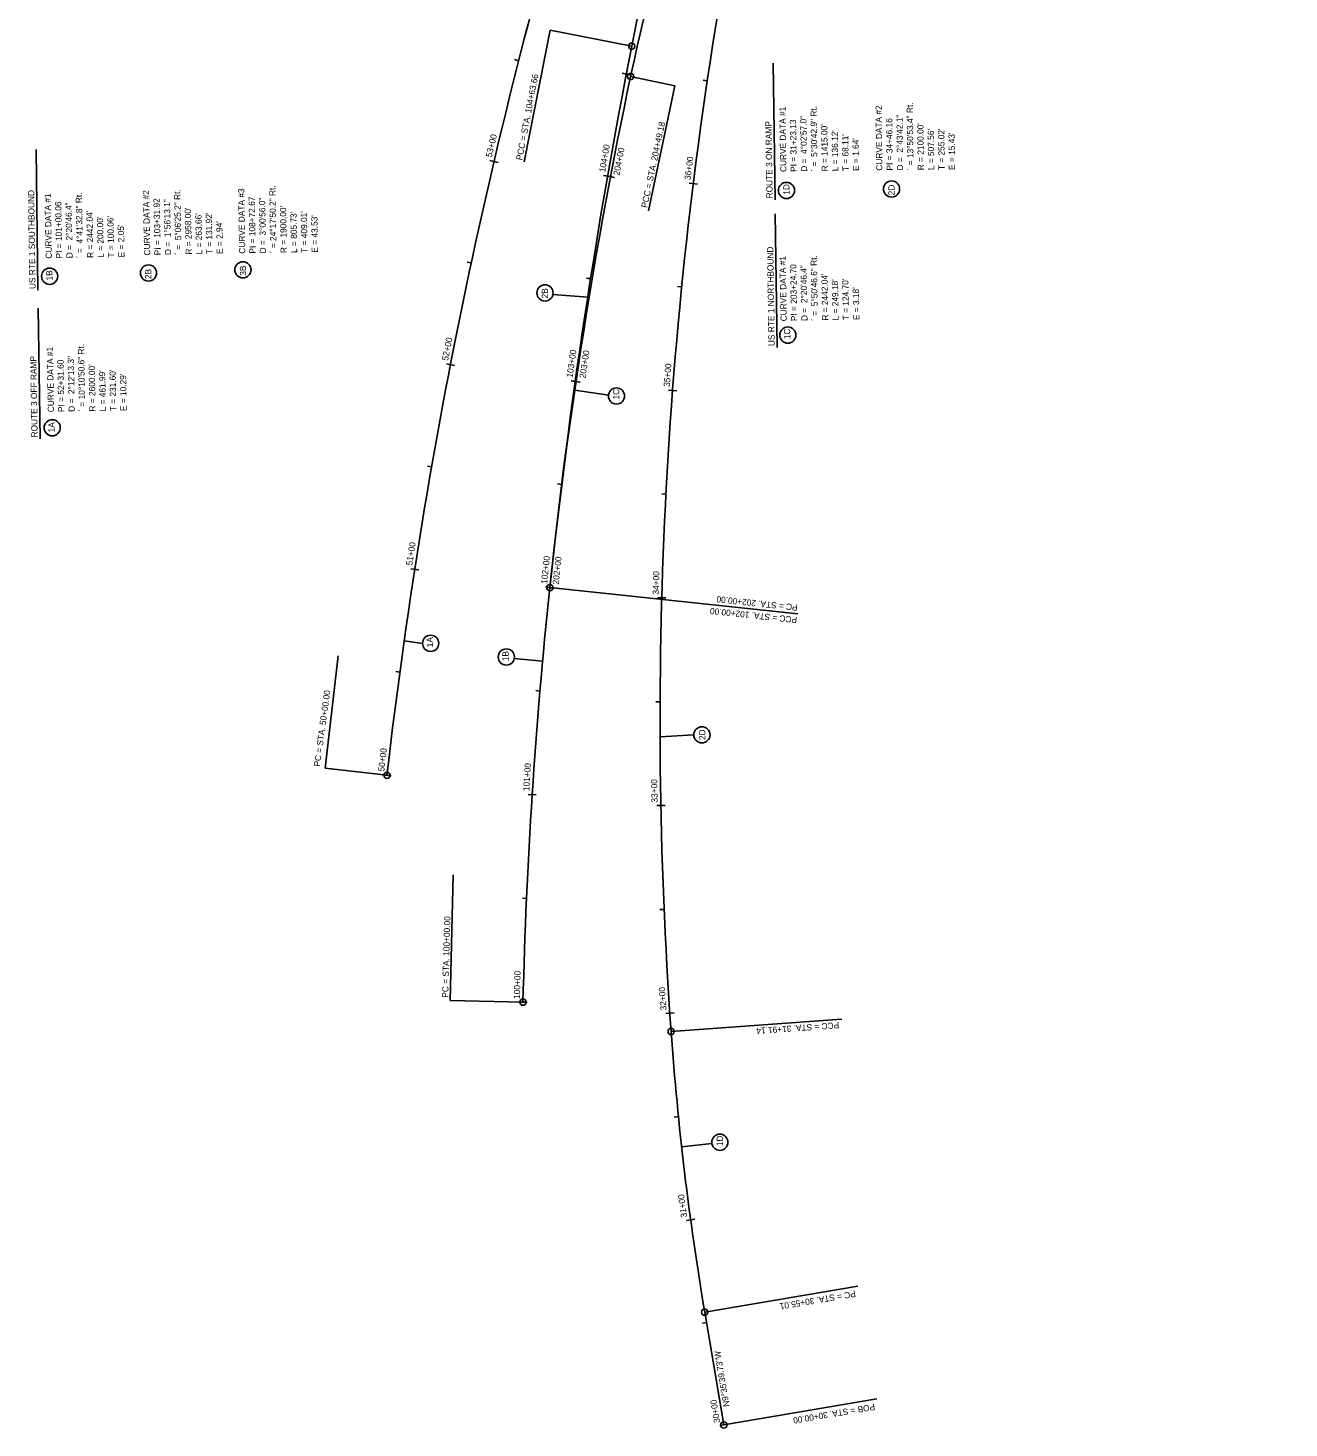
# Model space of a CAD drawing. Extents: x 1667099 to 1669772, y 337408 to 340124.
# Drawn here: x 1667099 to 1667706, y 337408 to 338082 of the extents above; entities that cross this region are included whole.
import ezdxf

# ---------------------------------------------------------------- set-up
doc = ezdxf.new("R2010")
doc.units = 0
for name, color, linetype in [('Alignment', 7, 'Continuous'), ('ANNOTATION', 7, 'Continuous'), ('D_Roadway_Centerline', 7, 'Continuous'), ('D_Roadway_Centerline_Bearings', 7, 'Continuous'), ('D_Roadway_Centerline_CurveData', 7, 'Continuous'), ('D_Roadway_Centerline_Flags', 7, 'Continuous'), ('D_Roadway_Centerline_Text', 7, 'Continuous'), ('S_Roadway_Edge_Pavement', 7, 'Continuous')]:
    doc.layers.add(name, color=color, linetype=linetype)

msp = doc.modelspace()

# ---------------------------------------------------------------- linework, layer by layer
at = {"layer": 'Alignment'}
msp.add_line((1667434.31, 337409.38), (1667425.14, 337463.63), dxfattribs=at)
for centre, radius, start, end in [((1668999.64, 337703.58), 1648.86, 162.88335, 167.57328), ((1669854.92, 337423.57), 2600, 163.22657, 173.40729), ((1669503.61, 337748.23), 2100, 170.2343, 184.08246), ((1669778.96, 337554.79), 2442.04, 168.09878, 173.94506), ((1668820.35, 337699.47), 1415, 184.08246, 189.59437)]:
    msp.add_arc(centre, radius, start, end, dxfattribs=at)
at = {"layer": 'ANNOTATION'}
for p, q in [((1667458.98, 337999.1), (1667458.07, 338064.76)), ((1667104.07, 337955.48), (1667103.13, 338023.31)), ((1667459.96, 337928.02), (1667459.07, 337992.36)), ((1667352.05, 337953.49), (1667368.76, 337952.25)), ((1667105.06, 337884.03), (1667104.19, 337946.87)), ((1667378.75, 337905.02), (1667362.51, 337907.39)), ((1667289.28, 337785.5), (1667280.41, 337786.75)), ((1667333.44, 337778.22), (1667347.05, 337776.98)), ((1667419.86, 337741.46), (1667403.63, 337740.54)), ((1667428.55, 337544.75), (1667413.87, 337543.27))]:
    msp.add_line(p, q, dxfattribs=at)
for centre in [(1667464.47, 338003.55), (1667515.07, 338004.24), (1667109.68, 337962.24), (1667157.3, 337963.83), (1667202.76, 337965.33), (1667348.22, 337954.22), (1667465.14, 337933.93), (1667382.63, 337904.6), (1667110.94, 337889.31), (1667293.18, 337785.55), (1667329.61, 337778.96), (1667423.76, 337741.51), (1667432.4, 337545.42)]:
    msp.add_circle(centre, 3.9, dxfattribs=at)
at = {"layer": 'D_Roadway_Centerline'}
msp.add_line((1667434.31, 337409.38), (1667425.14, 337463.63), dxfattribs=at)
for centre, radius, start, end in [((1669254.06, 337705.17), 1900, 144.54079, 168.83807), ((1668999.64, 337703.58), 1648.86, 162.88335, 167.57328), ((1669854.92, 337423.57), 2600, 163.22657, 173.40729), ((1669503.61, 337748.23), 2100, 170.2343, 184.08246), ((1670292.04, 337500.36), 2958, 168.83807, 173.94506), ((1669778.96, 337554.79), 2442.04, 168.09878, 173.94506), ((1669778.96, 337554.79), 2442.04, 173.94506, 178.63751), ((1668820.35, 337699.47), 1415, 184.08246, 189.59437)]:
    msp.add_arc(centre, radius, start, end, dxfattribs=at)
at = {"layer": 'D_Roadway_Centerline_Flags'}
for p, q in [((1667350.75, 338080.72), (1667338.23, 338017.24)), ((1667410.7, 338053.91), (1667398.02, 337993.75)), ((1667248.56, 337779.58), (1667242.31, 337725.52)), ((1667302.62, 337613.68), (1667304.06, 337674.09))]:
    msp.add_line(p, q, dxfattribs=at)
for points in [[(1667350.75, 338080.72), (1667390, 338072.98)], [(1667389.41, 338058.4), (1667410.7, 338053.91)], [(1667350.54, 337812.38), (1667469.88, 337799.72)], [(1667350.54, 337812.38), (1667469.88, 337799.72)], [(1667242.31, 337725.52), (1667272.11, 337722.07)], [(1667302.62, 337613.68), (1667337.61, 337612.85)], [(1667408.94, 337598.73), (1667491.21, 337604.6)], [(1667425.14, 337463.63), (1667498.87, 337476.09)], [(1667508.04, 337421.85), (1667434.31, 337409.38)]]:
    msp.add_lwpolyline(points, dxfattribs=at)
for centre in [(1667390, 338072.98), (1667389.41, 338058.4), (1667350.54, 337812.38), (1667350.54, 337812.38), (1667272.11, 337722.07), (1667337.61, 337612.85), (1667408.94, 337598.73), (1667425.14, 337463.63), (1667434.31, 337409.38)]:
    msp.add_circle(centre, 1.5, dxfattribs=at)
at = {"layer": 'D_Roadway_Centerline_Text'}
for points in [[(1667333.6, 338066.5), (1667335.54, 338066.01)], [(1667385.42, 338059.95), (1667387.38, 338059.57)], [(1667387.64, 338059.63), (1667389.59, 338059.2)], [(1667424.36, 338056.64), (1667426.34, 338056.35)], [(1667321.71, 338017.9), (1667325.6, 338016.99)], [(1667376.38, 338010.74), (1667380.32, 338010.05)], [(1667377.79, 338010.55), (1667381.72, 338009.8)], [(1667417.61, 338007.06), (1667421.58, 338006.56)], [(1667310.75, 337969.08), (1667312.7, 337968.66)], [(1667368.17, 337961.39), (1667370.14, 337961.08)], [(1667368.96, 337961.29), (1667370.94, 337960.96)], [(1667412.04, 337957.32), (1667414.03, 337957.12)], [(1667300.73, 337920.05), (1667304.65, 337919.29)], [(1667360.79, 337911.9), (1667364.75, 337911.34)], [(1667361.15, 337911.87), (1667365.1, 337911.28)], [(1667407.65, 337907.47), (1667411.64, 337907.16)], [(1667291.65, 337870.85), (1667293.62, 337870.5)], [(1667354.25, 337862.3), (1667356.24, 337862.05)], [(1667354.34, 337862.29), (1667356.33, 337862.04)], [(1667404.46, 337857.52), (1667406.45, 337857.42)], [(1667283.53, 337821.47), (1667287.48, 337820.86)], [(1667348.56, 337812.59), (1667352.53, 337812.17)], [(1667348.56, 337812.59), (1667352.53, 337812.17)], [(1667402.45, 337807.52), (1667406.45, 337807.4)], [(1667276.35, 337771.95), (1667278.33, 337771.68)], [(1667343.79, 337762.78), (1667345.78, 337762.61)], [(1667401.63, 337757.48), (1667403.63, 337757.47)], [(1667270.13, 337722.3), (1667274.1, 337721.84)], [(1667340.04, 337712.88), (1667344.03, 337712.62)], [(1667402.01, 337707.43), (1667406.01, 337707.51)], [(1667337.31, 337662.91), (1667339.31, 337662.82)], [(1667403.58, 337657.41), (1667405.57, 337657.5)], [(1667335.61, 337612.9), (1667339.61, 337612.8)], [(1667406.33, 337607.44), (1667410.33, 337607.71)], [(1667410.48, 337557.55), (1667412.47, 337557.75)], [(1667416.37, 337507.83), (1667420.33, 337508.37)], [(1667424.01, 337458.35), (1667425.98, 337458.69)], [(1667432.34, 337409.05), (1667436.29, 337409.72)]]:
    msp.add_lwpolyline(points, dxfattribs=at)
at = {"layer": 'S_Roadway_Edge_Pavement'}
for centre, radius, start, end in [((1669254.06, 337705.17), 1900, 144.54079, 168.83807), ((1670292.04, 337500.36), 2958, 168.83807, 173.94506), ((1669778.96, 337554.79), 2442.04, 173.94506, 178.63751)]:
    msp.add_arc(centre, radius, start, end, dxfattribs=at)

# ---------------------------------------------------------------- texts
at = {"layer": 'ANNOTATION'}
for s, rotation, p in [('ROUTE 3 ON RAMP', 90.79092, (1667457.82, 337999.72)), ('US RTE 1 SOUTHBOUND', 90.79092, (1667102.91, 337956.1)), ('1D', 90.79092, (1667465.98, 338001.48)), ('2D', 90.79092, (1667516.58, 338001.22)), ('US RTE 1 NORTHBOUND', 90.79092, (1667458.8, 337928.64)), ('1B', 90.79092, (1667111.09, 337960.22)), ('2B', 90.79092, (1667158.68, 337960.88)), ('3B', 91.23053, (1667204.34, 337962.52)), ('2B', 90.79092, (1667349.65, 337951.57)), ('1C', 90.79092, (1667466.3, 337931.96)), ('ROUTE 3 OFF RAMP', 90.79092, (1667103.9, 337884.66)), ('1C', 90.79092, (1667383.99, 337902.91)), ('1A', 90.79092, (1667112.1, 337887.08)), ('1A', 90.79092, (1667294.3, 337783.67)), ('1B', 90.79092, (1667330.72, 337776.99)), ('2D', 90.79092, (1667425.47, 337739.02)), ('1D', 90.79092, (1667433.88, 337543.56))]:
    msp.add_text(s, height=3, rotation=rotation, dxfattribs=at).set_placement(p)
at = {"layer": 'D_Roadway_Centerline_Bearings'}
msp.add_text('N9%%d35\'39.73"W', height=3, rotation=99.59437, dxfattribs=at).set_placement((1667437.12, 337418.38))
at = {"layer": 'D_Roadway_Centerline_CurveData'}
for s, rotation, p in [('CURVE DATA #1', 90.81635, (1667464.46, 338012.44)), ('´ =  5%%d30\'42.9" Rt.', 90.81635, (1667479.46, 338012.65)), ('CURVE DATA #2', 90.54783, (1667510.66, 338013.08)), ('´ = 13%%d50\'53.4" Rt.', 90.54783, (1667525.66, 338013.22)), ('PI = 31+23.13', 90.81635, (1667469.46, 338012.51)), ('D =  4%%d02\'57.0"', 90.81635, (1667474.46, 338012.58)), ('PI = 34+46.16', 90.54783, (1667515.66, 338013.13)), ('D =  2%%d43\'42.1"', 90.54783, (1667520.66, 338013.17)), ("R = 1415.00'", 90.81635, (1667484.46, 338012.73)), ("L = 136.12'", 90.81635, (1667489.46, 338012.8)), ("T = 68.11'", 90.81635, (1667494.46, 338012.87)), ("R = 2100.00'", 90.54783, (1667530.66, 338013.27)), ("L = 507.56'", 90.54783, (1667535.66, 338013.32)), ("T = 255.02'", 90.54783, (1667540.66, 338013.37)), ("E = 15.43'", 90.54783, (1667545.66, 338013.41)), ("E = 1.64'", 90.81635, (1667499.46, 338012.94)), ('CURVE DATA #2', 91.13691, (1667158.19, 337972.28)), ('´ =  5%%d06\'25.2" Rt.', 91.13691, (1667173.19, 337972.58)), ('CURVE DATA #3', 90.84556, (1667203.9, 337973.11)), ('´ = 24%%d17\'50.2" Rt.', 90.84556, (1667218.9, 337973.33)), ('CURVE DATA #1', 91.03265, (1667110.77, 337970.74)), ('PI = 101+00.06', 91.03265, (1667115.77, 337970.83)), ('D =  2%%d20\'46.4"', 91.03265, (1667120.77, 337970.92)), ('´ =  4%%d41\'32.8" Rt.', 91.03265, (1667125.77, 337971.01)), ('PI = 103+31.92', 91.13691, (1667163.19, 337972.38)), ('D =  1%%d56\'13.1"', 91.13691, (1667168.19, 337972.48)), ('PI = 108+72.67', 90.84556, (1667208.9, 337973.18)), ('D =  3%%d00\'56.0"', 90.84556, (1667213.9, 337973.26)), ("R = 2442.04'", 91.03265, (1667130.77, 337971.1)), ("L = 200.00'", 91.03265, (1667135.77, 337971.19)), ("T = 100.06'", 91.03265, (1667140.77, 337971.28)), ("R = 2958.00'", 91.13691, (1667178.19, 337972.68)), ("L = 263.66'", 91.13691, (1667183.18, 337972.78)), ("T = 131.92'", 91.13691, (1667188.18, 337972.88)), ("R = 1900.00'", 90.84556, (1667223.9, 337973.41)), ("L = 805.73'", 90.84556, (1667228.9, 337973.48)), ("T = 409.01'", 90.84556, (1667233.9, 337973.55)), ("E = 43.53'", 90.84556, (1667238.9, 337973.63)), ("E = 2.05'", 91.03265, (1667145.76, 337971.37)), ("E = 2.94'", 91.13691, (1667193.18, 337972.98)), ('CURVE DATA #1', 90.96311, (1667464.63, 337940.57)), ('´ =  5%%d50\'46.6" Rt.', 90.96311, (1667479.63, 337940.83)), ('PI = 203+24.70', 90.96311, (1667469.63, 337940.66)), ('D =  2%%d20\'46.4"', 90.96311, (1667474.63, 337940.74)), ("R = 2442.04'", 90.96311, (1667484.63, 337940.91)), ("L = 249.18'", 90.96311, (1667489.63, 337941)), ("T = 124.70'", 90.96311, (1667494.63, 337941.08)), ("E = 3.18'", 90.96311, (1667499.63, 337941.16)), ('´ = 10%%d10\'50.6" Rt.', 90.91268, (1667126.79, 337897.07)), ('CURVE DATA #1', 90.91268, (1667111.79, 337896.83)), ('D =  2%%d12\'13.3"', 90.91268, (1667121.79, 337896.99)), ('PI = 52+31.60', 90.91268, (1667116.79, 337896.91)), ("R = 2600.00'", 90.91268, (1667131.79, 337897.15)), ("L = 461.99'", 90.91268, (1667136.79, 337897.23)), ("T = 231.60'", 90.91268, (1667141.79, 337897.31)), ("E = 10.29'", 90.91268, (1667146.79, 337897.39))]:
    msp.add_text(s, height=3, rotation=rotation, dxfattribs=at).set_placement(p)
at = {"layer": 'D_Roadway_Centerline_Flags'}
for s, rotation, p in [('PCC = STA. 104+63.66', 79.20181, (1667337.19, 338017.9)), ('PCC = STA. 204+49.18', 78.09878, (1667397.42, 337994.99)), ('PC = STA. 202+00.00', 173.94506, (1667470, 337804.19)), ('PCC = STA. 102+00.00', 173.94506, (1667469.72, 337798.23)), ('PC = STA. 50+00.00', 82.15547, (1667239.83, 337726.08)), ('PC = STA. 100+00.00', 88.46468, (1667301.61, 337614.95)), ('PCC = STA. 31+91.14', 184.08246, (1667489.73, 337603.29)), ('PC = STA. 30+55.01', 189.59437, (1667497.51, 337474.02)), ('POB = STA. 30+00.00', 189.59437, (1667506.84, 337419.58))]:
    msp.add_text(s, height=3, rotation=rotation, dxfattribs=at).set_placement(p)
at = {"layer": 'D_Roadway_Centerline_Text'}
for s, rotation, p in [('53+00', 76.79624, (1667322.54, 338019.25)), ('104+00', 80.07111, (1667377.13, 338012.13)), ('204+00', 79.25261, (1667384.01, 338010.61)), ('36+00', 82.92713, (1667418.29, 338008.48)), ('52+00', 78.99992, (1667301.5, 337921.43)), ('103+00', 82.00808, (1667361.49, 337913.32)), ('203+00', 81.59884, (1667367.67, 337912.99)), ('35+00', 85.65551, (1667408.27, 337908.92)), ('51+00', 81.20361, (1667284.25, 337822.88)), ('102+00', 83.94506, (1667349.21, 337814.03)), ('202+00', 83.94506, (1667354.82, 337813.77)), ('34+00', 88.38388, (1667402.99, 337809)), ('50+00', 83.40729, (1667270.8, 337723.74)), ('101+00', 86.29129, (1667340.64, 337714.34)), ('33+00', 91.11225, (1667402.48, 337708.94)), ('100+00', 88.63751, (1667336.15, 337614.39)), ('32+00', 93.84062, (1667406.73, 337608.97)), ('31+00', 97.77271, (1667416.66, 337509.38)), ('30+00', 99.59437, (1667432.58, 337410.61))]:
    msp.add_text(s, height=3, rotation=rotation, dxfattribs=at).set_placement(p)

doc.saveas('drawing.dxf')
